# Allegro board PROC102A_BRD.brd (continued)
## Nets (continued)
DGND: C1.1 C2.2 C3.2 C4.2 C5.2 C6.2 C7.2 C8.2 C9.2 C10.2 C15.2 C16.2 C17.2 C20.2 C21.2 C22.2 C25.2 C26.2 C27.2 C30.2 C31.2 C32.2 C33.2 C34.2 C35.2 C44.2 C45.2 C46.2 C63.2 C64.2 C65.2 C66.2 C67.2 C68.2 C69.2 C70.2 C71.2 C72.2 C73.2 C74.2 C75.2 C76.2 C77.2 C78.2 C79.2 C80.2 C81.2 C82.2 C83.2 C84.2 C85.2 C86.2 C87.2 C88.2 C89.2 C90.2 C91.2 C92.2 C93.2 C94.2 C95.2 C96.2 C97.2 C98.2 C99.2 C100.2 C101.2 C102.2 C103.2 C104.2 C105.2 C106.2 C107.2 C108.2 C109.2 D13.1(K) D14.1(K) D15.2(ANODE) DN1.3 DN2.3 DN3.3 DN4.3 DN5.3 DN6.3 DN7.3 DN8.3 J1.A6 J1.A10 J1.A16 J1.A18 J1.A23 J1.A24 J1.A25 J1.B3 J1.B5 J1.B6 J1.B10 J1.B16 J1.B18 J1.B19 J1.B23 J1.B25 J1.B26 J1.B27 J1.B28 J1.B30 J1.C4 J1.C7 J1.C10 J1.C13 J1.C16 J1.C17 J1.C18 J1.C19 J1.C20 J1.C25 J1.C30 J1.D4 J1.D7 J1.D10 J1.D13 J1.D16 J1.D20 J1.D25 J1.D30 J1.E5 J1.E6 J1.E7 J1.E10 J1.E16 J1.E20 J1.E22 J1.E25 J1.E28 J1.E29 J2.2 J2.4 J2.6 J2.8 J2.10 J2.12 J2.14 J2.16 J2.18 J2.20 J3.2 J3.4 J3.6 J3.8 J3.10 J3.12 J3.14 J3.16 J3.18 J3.20 J4.2 J4.4 J4.6 J4.8 J4.10 J4.12 J4.14 J4.16 J4.18 J4.20 J5.2 J5.4 J5.6 J5.8 J5.10 J5.12 J5.14 J5.16 J5.18 J5.20 J6.2 J6.4 J6.6 J6.8 J6.10 J6.12 J6.14 J6.16 J6.18 J6.20 J7.2 J7.4 J7.6 J7.8 J7.10 J7.12 J7.14 J7.16 J7.18 J7.20 J8.2 J8.4 J8.6 J8.8 J8.10 J8.12 J8.14 J8.16 J8.18 J8.20 J9.2 J9.4 J9.6 J9.8 J9.10 J9.12 J9.14 J9.16 J9.18 J9.20 J11.3 J13.2 J13.3 J17.2 J17.4 J17.6 J18.5 J21.9 LD3.1(CATHODE) LD4.1(CATHODE) LD22.1(CATHODE) Q1.2(S) Q2.2(S) Q3.2(S) R1.1 R6.2 R7.2 R8.2 R69.2 R70.2 R73.2 R74.2 R75.2 R78.2 R79.2 R80.2 R82.2 R84.2 R85.2 R86.2 R87.2 R90.2 R91.2 R92.2 R93.2 R96.2 R97.2 R104.2 R105.2 R106.1 R107.2 R108.2 R109.1 R123.1 R124.1 R125.2 TP4.1(TP) TP5.1(TP) TP6.1(TP) TP36.1(TP) U1.4(VSS) U2.3(GND#3) U2.5(GND#5) U2.7(GND#7) U2.9(GND#9) U2.11(GND#11) U2.13(GND#13) U2.16(GND#16) U2.18(GND#18) U2.20(GND#20) U2.22(GND#22) U2.27(GND#27) U2.30(GND#30) U2.33(GND#33) U2.37(GND#37) U2.40(GND#40) U2.43(GND#43) U2.46(GND#46) U4.3(GND#3) U4.5(GND#5) U4.7(GND#7) U4.9(GND#9) U4.11(GND#11) U4.13(GND#13) U4.16(GND#16) U4.18(GND#18) U4.20(GND#20) U4.22(GND#22) U4.27(GND#27) U4.30(GND#30) U4.33(GND#33) U4.37(GND#37) U4.40(GND#40) U4.43(GND#43) U4.46(GND#46) U7.3(GND#3) U7.5(GND#5) U7.7(GND#7) U7.9(GND#9) U7.11(GND#11) U7.13(GND#13) U7.16(GND#16) U7.18(GND#18) U7.20(GND#20) U7.22(GND#22) U7.27(GND#27) U7.30(GND#30) U7.33(GND#33) U7.37(GND#37) U7.40(GND#40) U7.43(GND#43) U7.46(GND#46) U9.3(GND#3) U9.5(GND#5) U9.7(GND#7) U9.9(GND#9) U9.11(GND#11) U9.13(GND#13) U9.16(GND#16) U9.18(GND#18) U9.20(GND#20) U9.22(GND#22) U9.27(GND#27) U9.30(GND#30) U9.33(GND#33) U9.37(GND#37) U9.40(GND#40) U9.43(GND#43) U9.46(GND#46) U11.3(GND#3) U11.5(GND#5) U11.7(GND#7) U11.9(GND#9) U11.11(GND#11) U11.13(GND#13) U11.16(GND#16) U11.18(GND#18) U11.20(GND#20) U11.22(GND#22) U11.27(GND#27) U11.30(GND#30) U11.33(GND#33) U11.37(GND#37) U11.40(GND#40) U11.43(GND#43) U11.46(GND#46) U12.3(GND#3) U12.5(GND#5) U12.7(GND#7) U12.9(GND#9) U12.11(GND#11) U12.13(GND#13) U12.16(GND#16) U12.18(GND#18) U12.20(GND#20) U12.22(GND#22) U12.27(GND#27) U12.30(GND#30) U12.33(GND#33) U12.37(GND#37) U12.40(GND#40) U12.43(GND#43) U12.46(GND#46) U17.3(GND#3) U17.5(GND#5) U17.7(GND#7) U17.9(GND#9) U17.11(GND#11) U17.13(GND#13) U17.16(GND#16) U17.18(GND#18) U17.20(GND#20) U17.22(GND#22) U17.27(GND#27) U17.30(GND#30) U17.33(GND#33) U17.37(GND#37) U17.40(GND#40) U17.43(GND#43) U17.46(GND#46) U26.1(GND) U26.21(BLANK) U27.7(L-) U27.11(EP) U28.7(L-) U28.11(EP) U29.7(L-) U29.11(EP) U30.7(L-) U30.11(EP) U31.7(L-) U31.11(EP) U32.7(L-) U32.11(EP) U33.7(L-) U33.11(EP) U34.7(L-) U34.11(EP) U35.1(GND#1) U35.12(GND#12) U35.29(EP) U36.1(GND#1) U36.12(GND#12) U36.29(EP) U37.28(GND) U37.29(EP) U38.3(GND) U39.6(GND) U39.10(REF2) U39.11(REF1)
VCC1V8_HSE: C2.1 C3.1 J1.C2 J1.C3 J17.5 R71.1 TP3.1(TP)
VCC3V3_IO_HSE: C1.2 C4.1 C5.1 C8.1 C9.1 C10.1 C15.1 C16.1 C17.1 C20.1 C21.1 C22.1 C25.1 C26.1 C27.1 C30.1 C31.1 C32.1 C33.1 C34.1 C35.1 C44.1 C45.1 C46.1 C63.1 C64.1 C65.1 C72.1 C73.1 C78.1 C81.1 C82.1 C85.1 C106.1 C107.1 J1.A27 J1.A28 J1.A29 J11.1 J17.3 LD6.2(ANODE) LD7.2(ANODE) LD8.2(ANODE) LD9.2(ANODE) LD10.2(ANODE) LD11.2(ANODE) LD12.2(ANODE) LD13.2(ANODE) LD14.2(ANODE) LD15.2(ANODE) LD16.2(ANODE) LD17.2(ANODE) LD18.2(ANODE) LD19.2(ANODE) LD20.2(ANODE) LD21.2(ANODE) R2.1 R3.1 R4.1 R5.1 R64.1 R65.1 R67.1 R68.1 R76.2 R77.2 R81.2 R83.2 R88.2 R89.2 R94.2 R95.2 R98.2 R99.1 R100.2 R101.2 R102.1 R103.2 R120.1 TP2.1(TP) U1.8(VCC) U2.1(VDD#1) U2.6(VDD#6) U2.12(VDD#12) U2.19(VDD#19) U2.36(VDD#36) U4.1(VDD#1) U4.6(VDD#6) U4.12(VDD#12) U4.19(VDD#19) U4.36(VDD#36) U7.1(VDD#1) U7.6(VDD#6) U7.12(VDD#12) U7.19(VDD#19) U7.36(VDD#36) U9.1(VDD#1) U9.6(VDD#6) U9.12(VDD#12) U9.19(VDD#19) U9.36(VDD#36) U11.1(VDD#1) U11.6(VDD#6) U11.12(VDD#12) U11.19(VDD#19) U11.36(VDD#36) U12.1(VDD#1) U12.6(VDD#6) U12.12(VDD#12) U12.19(VDD#19) U12.36(VDD#36) U17.1(VDD#1) U17.6(VDD#6) U17.12(VDD#12) U17.19(VDD#19) U17.36(VDD#36) U26.24(VCC) U27.1(VCC_IN/OUT) U28.1(VCC_IN/OUT) U29.1(VCC_IN/OUT) U30.1(VCC_IN/OUT) U31.1(VCC_IN/OUT) U32.1(VCC_IN/OUT) U33.1(VCC_IN/OUT) U34.1(VCC_IN/OUT) U39.9(VS)
VCC_5V0_HSE: C6.1 C7.1 J1.A1 J1.A2 J1.A3 J17.1 R66.1 TP1.1(TP)
VCC_24V0: C66.1 C67.1 C68.1 C69.1 C70.1 C71.1 C74.1 C75.1 C76.1 C77.1 C79.1 C80.1 C83.1 C84.1 C86.1 C87.1 C88.1 C89.1 C108.1 C109.1 J21.1 R130.2 TP37.1(TP) U27.9(L+) U28.9(L+) U29.9(L+) U30.9(L+) U31.9(L+) U32.9(L+) U33.9(L+) U34.9(L+) U35.20(VS#20) U35.21(VS#21) U35.22(VS#22) U35.23(VS#23) U36.20(VS#20) U36.21(VS#21) U36.22(VS#22) U36.23(VS#23) U39.1(IS-_1) U39.2(IS-_2) U39.3(IS-_3)
AIN_0: C105.1 D10.2(A) J12.15 R128.2
AIN_2: C103.1 J12.6 R126.1
AIN_4: C104.1 D9.2(A) J12.10 R127.1
CQ_1: D1.2(A) DN1.4 U27.8(CQ)
CQ_2: D2.2(A) DN2.4 U28.8(CQ)
CQ_3: D4.2(A) DN3.4 U30.8(CQ)
CQ_4: D3.2(A) DN4.4 U29.8(CQ)
CQ_5: D6.2(A) DN5.4 U31.8(CQ)
CQ_6: D5.2(A) DN6.4 U32.8(CQ)
CQ_7: D8.2(A) DN7.4 U33.8(CQ)
CQ_8: D7.2(A) DN8.4 U34.8(CQ)
DI_1: DN1.2 J21.3 R111.1
DI_2: DN2.2 J21.2 R112.1
DI_3: DN3.2 J21.5 R113.1
DI_4: DN4.2 J21.4 R114.1
DI_5: DN5.2 J21.7 R115.1
DI_6: DN6.2 J21.6 R116.1
DI_7: DN7.2 J21.8 R117.1
DI_8: DN8.2 J21.10 R118.1
EEPROM0_A0: R2.2 R6.1 U1.1(A0)
EEPROM0_A1: R3.2 R7.1 U1.2(A1)
EEPROM0_A2: R4.2 R8.1 U1.3(A2)
EEPROM0_WP: R5.2 U1.7(WP)
EN_L+1: U7.44(1B2) U36.5(IN3)
EN_L+2: U7.39(2B2) U36.6(IN4)
EN_L+3: U7.32(4B2) U36.4(IN2)
EN_L+4: U7.31(5B2) U36.3(IN1)
EN_L+5: U7.45(0B2) U35.5(IN3)
EN_L+6: U7.26(6B2) U35.6(IN4)
EN_L+7: U7.38(3B2) U35.4(IN2)
EN_L+8: U7.25(7B2) U35.3(IN1)
EN_PHY_1: TP9.1(TP) U9.45(0B2) U27.5(EN)
EN_PHY_2: TP12.1(TP) U9.44(1B2) U28.5(EN)
EN_PHY_3: TP15.1(TP) U9.39(2B2) U30.5(EN)
EN_PHY_4: TP18.1(TP) U9.38(3B2) U29.5(EN)
EN_PHY_5: TP21.1(TP) U9.32(4B2) U31.5(EN)
EN_PHY_6: TP24.1(TP) U9.31(5B2) U32.5(EN)
EN_PHY_7: TP27.1(TP) U9.26(6B2) U33.5(EN)
EN_PHY_8: TP30.1(TP) U9.25(7B2) U34.5(EN)
FAULT_1: R76.1 U11.45(0B2) U27.2(NFAULT)
FAULT_2: R77.1 U11.44(1B2) U28.2(NFAULT)
FAULT_3: R83.1 U11.39(2B2) U30.2(NFAULT)
FAULT_4: R81.1 U11.38(3B2) U29.2(NFAULT)
FAULT_5: R89.1 U11.32(4B2) U31.2(NFAULT)
FAULT_6: R88.1 U11.31(5B2) U32.2(NFAULT)
FAULT_7: R95.1 U11.26(6B2) U33.2(NFAULT)
FAULT_8: R94.1 U11.25(7B2) U34.2(NFAULT)
GPMC0_AD0: J1.E14 U11.2(A0)
GPMC0_AD0_HDR: J6.1 U11.48(0B1)
GPMC0_AD1: J1.D14 U11.4(A1)
GPMC0_AD1_HDR: J6.3 U11.47(1B1)
GPMC0_AD2: J1.C14 U11.8(A2)
GPMC0_AD2_HDR: J6.5 U11.42(2B1)
GPMC0_AD3: J1.E15 U11.10(A3)
GPMC0_AD3_HDR: J6.7 U11.41(3B1)
GPMC0_AD4: J1.D15 U11.15(A4)
GPMC0_AD4_HDR: J6.9 U11.35(4B1)
GPMC0_AD5: J1.C15 U11.17(A5)
GPMC0_AD5_HDR: J6.11 U11.34(5B1)
GPMC0_AD6: J1.E17 U11.21(A6)
GPMC0_AD6_HDR: J6.13 U11.29(6B1)
GPMC0_AD7: J1.D17 U11.23(A7)
GPMC0_AD7_HDR: J6.15 U11.28(7B1)
GPMC0_AD8: J1.A22 J6.17
GPMC0_AD9: J1.A21 J6.19
GPMC0_AD10: J1.B21 J7.1
GPMC0_AD11: J1.E21 J7.3
GPMC0_AD12: J1.C21 J7.5
GPMC0_AD13: J1.D21 J7.7
GPMC0_AD14: J1.B20 J7.9
GPMC0_AD15: J1.A19 J7.11
GPMC0_CSN1: J1.E19 J7.17
GPMC0_CSN2: J1.D18 J7.13
GPMC0_CSN3: J1.D19 J7.15
GPMC0_DIR: J1.E18 J7.19
H_CS: R105.1 R128.1 U35.10(CS)
H_DIAG: R100.1 U35.14(DIAG_EN)
H_FAULT: R99.2 U12.26(6B2) U35.9(F\A\U\L\T\)
H_SEH: U12.32(4B2) U35.7(SEH)
H_SEL: U12.31(5B2) U35.8(SEL)
H_THERM: R98.1 R106.2 U35.13(THER)
HSE_DETECT: J1.E4 R1.2
HSE_GPIO0_31: J1.B22 U12.15(A4)
HSE_GPIO0_31_HDR: J8.1 U12.35(4B1)
HSE_GPIO0_32: J1.C22 U12.17(A5)
HSE_GPIO0_32_HDR: J8.3 U12.34(5B1)
HSE_GPIO0_33: J1.D22 U12.21(A6)
HSE_GPIO0_33_HDR: J8.5 U12.29(6B1)
HSE_GPIO0_34: J1.C23 U12.10(A3)
HSE_GPIO0_34_HDR: J8.7 U12.41(3B1)
HSE_GPIO0_35: J1.B24 U12.4(A1)
HSE_GPIO0_35_HDR: J8.9 U12.47(1B1)
HSE_GPIO0_36: J1.A20 U12.2(A0)
HSE_GPIO0_36_HDR: J8.11 U12.48(0B1)
HSE_GPIO0_37: J1.C24 U12.8(A2)
HSE_GPIO0_37_HDR: J8.13 U12.42(2B1)
HSE_GPIO0_38: J1.E26 J8.15
HSE_GPIO0_39: J1.C26 J8.17
HSE_GPIO0_41: J1.D26 J8.19
HSE_MCAN0_RX/UART4_TXD: J1.E24 J3.19
HSE_MCAN0_TX/UART4_RXD: J1.D24 J3.17
HSE_MCAN1_RX/I2C3_SDA: J1.C29 J3.15
HSE_MCAN1_TX/I2C3_SCL: J1.D29 J3.13
IN+: U39.16(IN+) U39.17(SH+)
IN-: U39.4(SH-) U39.5(IN-)
IN_CS: R126.2 U39.13(OUT)
INPUT_24V0: D15.1(CATHODE) F1.2 R131.1 U39.18(IS+_1) U39.19(IS+_2) U39.20(IS+_3)
L+_1: DN1.1 U36.17(OUT3_1) U36.18(OUT3_2)
L+_2: DN2.1 U36.15(OUT4_1) U36.16(OUT4_2)
L+_3: DN3.1 U36.25(OUT2_1) U36.26(OUT2_2)
L+_4: DN4.1 U36.27(OUT1_1) U36.28(OUT1_2)
L+_5: DN5.1 U35.17(OUT3_1) U35.18(OUT3_2)
L+_6: DN6.1 U35.15(OUT4_1) U35.16(OUT4_2)
L+_7: DN7.1 U35.25(OUT2_1) U35.26(OUT2_2)
L+_8: DN8.1 U35.27(OUT1_1) U35.28(OUT1_2)
L_CS: R108.1 R127.2 U36.10(CS)
L_DIAG: R103.1 U36.14(DIAG_EN)
L_FAULT: R102.2 U12.45(0B2) U36.9(F\A\U\L\T\)
L_SEH: U12.38(3B2) U36.7(SEH)
L_SEL: U12.44(1B2) U36.8(SEL)
L_THERM: R101.1 R109.2 U36.13(THER)
LATCH: U17.39(2B2) U26.4(LAT)
LED_G1: LD21.1(CATHODE) U26.20(OUT15)
LED_G2: LD19.1(CATHODE) U26.18(OUT13)
LED_G3: LD17.1(CATHODE) U26.16(OUT11)
LED_G4: LD15.1(CATHODE) U26.14(OUT9)
LED_G5: LD13.1(CATHODE) U26.12(OUT7)
LED_G6: LD11.1(CATHODE) U26.10(OUT5)
LED_G7: LD9.1(CATHODE) U26.8(OUT3)
LED_G8: LD7.1(CATHODE) U26.6(OUT1)
LED_R1: LD20.1(CATHODE) U26.19(OUT14)
LED_R2: LD18.1(CATHODE) U26.17(OUT12)
LED_R3: LD16.1(CATHODE) U26.15(OUT10)
LED_R4: LD14.1(CATHODE) U26.13(OUT8)
LED_R5: LD12.1(CATHODE) U26.11(OUT6)
LED_R6: LD10.1(CATHODE) U26.9(OUT4)
LED_R7: LD8.1(CATHODE) U26.7(OUT2)
LED_R8: LD6.1(CATHODE) U26.5(OUT0)
LOAD_PULSE_SE: R121.1 U12.39(2B2)
MCU_PORZ: J1.E30 J18.6 TP33.1(TP)
MCU_RESETSTATZ: J1.E3 J18.4 TP32.1(TP)
MCU_RESETZ: J1.D3 J18.2 TP31.1(TP)
MUX_CONTROL_1: R72.1 U2.24(SEL) U4.24(SEL) U7.24(SEL) U9.24(SEL) U11.24(SEL) U12.24(SEL) U17.24(SEL)
PRG0_HSE_ETH1_CLK: J1.A17 J18.3 TP35.1(TP)
PRG0_HSE_ETH2_CLK: J1.B17 J18.1 TP34.1(TP)
PRG0_MDIO0_MDC: J1.A5 J5.19
PRG0_MDIO0_MDIO: J1.A4 J5.17
PRG0_PRU0GPO0: J1.B12 Q1.1(G) R69.1 U2.2(A0)
PRG0_PRU0GPO0_HDR: J2.1 U2.48(0B1)
PRG0_PRU0GPO1: J1.E8 U2.4(A1)
PRG0_PRU0GPO1_HDR: J2.3 U2.47(1B1)
PRG0_PRU0GPO2: J1.A8 U2.8(A2)
PRG0_PRU0GPO2_HDR: J2.5 U2.42(2B1)
PRG0_PRU0GPO3: J1.A9 U2.10(A3)
PRG0_PRU0GPO3_HDR: J2.7 U2.41(3B1)
PRG0_PRU0GPO4: J1.A13 U2.15(A4)
PRG0_PRU0GPO4_HDR: J2.9 U2.35(4B1)
PRG0_PRU0GPO5: J1.C6 U2.17(A5)
PRG0_PRU0GPO5_HDR: J2.11 U2.34(5B1)
PRG0_PRU0GPO6: J1.D8 U2.21(A6)
PRG0_PRU0GPO6_HDR: J2.13 U2.29(6B1)
PRG0_PRU0GPO7: J1.B7 U2.23(A7)
PRG0_PRU0GPO7_HDR: J2.15 U2.28(7B1)
PRG0_PRU0GPO8: J1.A7 U4.2(A0)
PRG0_PRU0GPO8_HDR: J2.17 U4.48(0B1)
PRG0_PRU0GPO11: J1.B14 U4.4(A1)
PRG0_PRU0GPO11_HDR: J2.19 U4.47(1B1)
PRG0_PRU0GPO12: J1.A14 U4.8(A2)
PRG0_PRU0GPO12_HDR: J3.1 U4.42(2B1)
PRG0_PRU0GPO13: J1.C5 U4.10(A3)
PRG0_PRU0GPO13_HDR: J3.3 U4.41(3B1)
PRG0_PRU0GPO14: J1.C9 U4.15(A4)
PRG0_PRU0GPO14_HDR: J3.5 U4.35(4B1)
PRG0_PRU0GPO15: J1.D12 U4.17(A5)
PRG0_PRU0GPO15_HDR: J3.7 U4.34(5B1)
PRG0_PRU0GPO16: J1.E9 U4.21(A6)
PRG0_PRU0GPO16_HDR: J3.9 U4.29(6B1)
PRG0_PRU0GPO17: J1.B8 U4.23(A7)
PRG0_PRU0GPO17_HDR: J3.11 U4.28(7B1)
PRG0_PRU0GPO18: J1.B9 U7.4(A1)
PRG0_PRU0GPO18_HDR: J4.1 U7.47(1B1)
PRG0_PRU0GPO19: J1.B11 U7.8(A2)
PRG0_PRU0GPO19_HDR: J4.3 U7.42(2B1)
PRG0_PRU1GPO0: J1.A12 Q2.1(G) R70.1 U7.15(A4)
PRG0_PRU1GPO0_HDR: J4.5 U7.35(4B1)
PRG0_PRU1GPO1: J1.A11 U7.17(A5)
PRG0_PRU1GPO1_HDR: J4.7 U7.34(5B1)
PRG0_PRU1GPO2: J1.D9 U7.2(A0)
PRG0_PRU1GPO2_HDR: J4.9 U7.48(0B1)
PRG0_PRU1GPO3: J1.C8 U7.21(A6)
PRG0_PRU1GPO3_HDR: J4.11 U7.29(6B1)
PRG0_PRU1GPO4: J1.B13 U7.10(A3)
PRG0_PRU1GPO4_HDR: J4.13 U7.41(3B1)
PRG0_PRU1GPO5: J1.D6 U7.23(A7)
PRG0_PRU1GPO5_HDR: J4.15 U7.28(7B1)
PRG0_PRU1GPO6: J1.E11 U9.2(A0)
PRG0_PRU1GPO6_HDR: J4.17 U9.48(0B1)
PRG0_PRU1GPO8: J1.B4 U9.4(A1)
PRG0_PRU1GPO8_HDR: J4.19 U9.47(1B1)
PRG0_PRU1GPO11: J1.D11 U9.8(A2)
PRG0_PRU1GPO11_HDR: J5.1 U9.42(2B1)
PRG0_PRU1GPO12: J1.B15 U9.10(A3)
PRG0_PRU1GPO12_HDR: J5.3 U9.41(3B1)
PRG0_PRU1GPO13: J1.D5 U9.15(A4)
PRG0_PRU1GPO13_HDR: J5.5 U9.35(4B1)
PRG0_PRU1GPO14: J1.E12 U9.17(A5)
PRG0_PRU1GPO14_HDR: J5.7 U9.34(5B1)
PRG0_PRU1GPO15: J1.C11 U9.21(A6)
PRG0_PRU1GPO15_HDR: J5.9 U9.29(6B1)
PRG0_PRU1GPO16: J1.A15 U9.23(A7)
PRG0_PRU1GPO16_HDR: J5.11 U9.28(7B1)
PRG1_PRU1GPO18: J1.E13 J5.13
PRG1_PRU1GPO19: J1.C12 J5.15
RX_1: TP8.1(TP) U2.45(0B2) U27.3(RX)
RX_2: TP11.1(TP) U2.44(1B2) U28.3(RX)
RX_3: TP14.1(TP) U2.39(2B2) U30.3(RX)
RX_4: TP17.1(TP) U2.38(3B2) U29.3(RX)
RX_5: TP20.1(TP) U2.32(4B2) U31.3(RX)
RX_6: TP23.1(TP) U2.31(5B2) U32.3(RX)
RX_7: TP26.1(TP) U2.26(6B2) U33.3(RX)
RX_8: TP29.1(TP) U2.25(7B2) U34.3(RX)
SOC_I2C0_SCL: J1.E1 U1.6(SCL)
SOC_I2C0_SDA: J1.E2 U1.5(SDA)
SOC_SPI1_CLK: J1.C1 U17.15(A4)
SOC_SPI1_CLK_HDR: J9.5 U17.35(4B1)
SOC_SPI1_CLK_SE/LED: R119.2 U17.32(4B2) U26.3(SCLK)
SOC_SPI1_CS0: J1.D1 U17.10(A3)
SOC_SPI1_CS0_HDR: J9.7 U17.41(3B1)
SOC_SPI1_CS0_SE: R122.1 U17.38(3B2)
SOC_SPI1_CS1: J1.D2 U17.8(A2)
SOC_SPI1_CS1_HDR: J9.9 U17.42(2B1)
SOC_SPI1_MISO: J1.B1 U17.2(A0)
SOC_SPI1_MISO_HDR: J9.1 U17.48(0B1)
SOC_SPI1_MISO_SE: R120.2 U17.45(0B2) U38.4(Y)
SOC_SPI1_MOSI: J1.B2 U17.4(A1)
SOC_SPI1_MOSI_HDR: J9.3 U17.47(1B1)
SOC_SPI1_MOSI_LED: U17.44(1B2) U26.2(SIN)
TX_1: D16.2(A) TP7.1(TP) U4.45(0B2) U27.4(TX)
TX_2: D17.2(A) TP10.1(TP) U4.44(1B2) U28.4(TX)
TX_3: D18.2(A) TP13.1(TP) U4.39(2B2) U30.4(TX)
TX_4: D19.2(A) TP16.1(TP) U4.38(3B2) U29.4(TX)
TX_5: D20.2(A) TP19.1(TP) U4.32(4B2) U31.4(TX)
TX_6: D21.2(A) TP22.1(TP) U4.31(5B2) U32.4(TX)
TX_7: D22.2(A) TP25.1(TP) U4.26(6B2) U33.4(TX)
TX_8: D23.2(A) TP28.1(TP) U4.25(7B2) U34.4(TX)
N16728800: R104.1 U35.11(CL)
N16729761: R107.1 U36.11(CL)
N16731521: C95.1 R111.2 U37.3(IP0)
N16731525: C96.1 R112.2 U37.5(IP1)
N16731545: C97.1 R113.2 U37.7(IP2)
N16731549: C98.1 R114.2 U37.9(IP3)
N16731553: C99.1 R115.2 U37.11(IP4)
N16731557: C100.1 R116.2 U37.18(IP5)
N16731561: C101.1 R117.2 U37.20(IP6)
N16731565: C102.1 R118.2 U37.22(IP7)
N16731823: R123.2 U37.1(DB0)
N16731831: R124.2 U37.2(DB1)
N16731839: R122.2 U37.24(C\E\)
N16731843: R125.1 U37.13(RLIM)
N16732073: C90.1 C91.1 R130.1 U37.14(VCC)
N16732201: U37.23(SOP) U38.2(A)
N16798390: R121.2 U37.26(L\D\)
N16811368: F1.1 J13.1
N16812824: D10.1(K) D12.2(A)
N16812834: D12.1(K) D14.2(A)
N16813069: D9.1(K) D11.2(A)
N16813071: D11.1(K) D13.2(A)
N16970041: R82.1 U30.6(ILIM_ADJ)
N16970059: D4.1(K) Q7.3(COLLECTOR)
N17109412: R119.1 U37.25(CLK)
N17175087: R74.1 U27.6(ILIM_ADJ)
N17175103: D1.1(K) Q4.3(COLLECTOR)
N17184096: R75.1 U28.6(ILIM_ADJ)
N17184112: D2.1(K) Q5.3(COLLECTOR)
N17184793: R80.1 U29.6(ILIM_ADJ)
N17184817: D3.1(K) Q6.3(COLLECTOR)
N17188199: J11.2 R72.2
N17189922: R73.1 U26.23(IREF)
N17190440: LD1.2(ANODE) R64.2
N17190442: LD1.1(CATHODE) Q1.3(D)
N17190473: LD2.2(ANODE) R65.2
N17190482: LD2.1(CATHODE) Q2.3(D)
N17190504: LD5.1(CATHODE) Q3.3(D)
N17190506: LD5.2(ANODE) R68.2
N17190525: Q3.1(G) R71.2
N17190539: LD4.2(ANODE) R67.2
N17190541: LD3.2(ANODE) R66.2
N17194207: R87.1 U32.6(ILIM_ADJ)
N17194223: D5.1(K) Q9.3(COLLECTOR)
N17194517: R86.1 U31.6(ILIM_ADJ)
N17194572: D6.1(K) Q8.3(COLLECTOR)
N17194628: R92.1 U34.6(ILIM_ADJ)
N17194647: D7.1(K) Q10.3(COLLECTOR)
N17196536: R93.1 U33.6(ILIM_ADJ)
N17196560: D8.1(K) Q11.3(COLLECTOR)
N17284137: D16.1(K) Q4.1(BASE)
N17284170: D17.1(K) Q5.1(BASE)
N17284203: D18.1(K) Q7.1(BASE)
N17284241: D19.1(K) Q6.1(BASE)
N17284279: D20.1(K) Q8.1(BASE)
N17284317: D21.1(K) Q9.1(BASE)
N17284361: D22.1(K) Q11.1(BASE)
N17284397: D23.1(K) Q10.1(BASE)
N169701040: Q7.2(EMITTER) R85.1
N169703320: LD22.2(ANODE) R131.2
N171751400: Q4.2(EMITTER) R78.1
N171841470: Q5.2(EMITTER) R79.1
N171847351: Q6.2(EMITTER) R84.1
N171943770: Q8.2(EMITTER) R90.1
N171944000: Q9.2(EMITTER) R91.1
N171947950: Q10.2(EMITTER) R96.1
N171966200: Q11.2(EMITTER) R97.1

Pads without a net: DN1 5; DN2 5; DN3 5; DN4 5; DN5 5; DN6 5; DN7 5; DN8 5; J1 A26 A30 B29 C27 C28 D23 D27 D28 E23 E27; J9 11 13 15 17 19; J12 1 2 3 4 5 7 8 9 11 12 13 14 16 17 18 19 20; NOREF#3 1; NOREF#5 1; NOREF#6 1; NOREF#7 1; NOREF#8 1; NOREF#9 1; NOREF#10 1; NOREF#11 1; NOREF#12 1; NOREF#13 1; NOREF#14 1; NOREF#15 1; NOREF#16 1; NOREF#17 1; NOREF#18 1; NOREF#19 1; NOREF#20 1; NOREF#21 1; NOREF#22 1; NOREF#23 1; NOREF#24 1; NOREF#25 1; NOREF#26 1; NOREF#27 1; NOREF#29 1; NOREF#30 1; NOREF#31 1; NOREF#32 1; NOREF#33 1; NOREF#34 1; NOREF#35 1; NOREF#36 1; NOREF#37 1; NOREF#38 1; NOREF#39 1; NOREF#40 1; NOREF#41 1; NOREF#42 1; NOREF#43 1; NOREF#44 1; NOREF#45 1; NOREF#46 1; NOREF#47 1; NOREF#48 1; NOREF#49 1; NOREF#50 1; NOREF#51 1; NOREF#52 1; NOREF#53 1; NOREF#54 1; NOREF#55 1; NOREF#56 1; NOREF#57 1; NOREF#60 1; NOREF#61 1; NOREF#62 1; NOREF#63 1; NOREF#64 1; NOREF#65 1; NOREF#66 1; NOREF#67 1; NOREF#68 1; NOREF#69 1; NOREF#71 1; NOREF#72 1; NOREF#73 1; NOREF#74 1; NOREF#75 1; NOREF#76 1; NOREF#77 1; NOREF#78 1; NOREF#79 1; NOREF#80 1; NOREF#82 1; NOREF#83 1; NOREF#84 1; NOREF#85 1; NOREF#86 1; NOREF#87 1; NOREF#88 1; NOREF#89 1; NOREF#90 1; NOREF#91 1; NOREF#92 1; NOREF#94 1; NOREF#95 1; NOREF#96 1; NOREF#97 1; NOREF#100 1; NOREF#101 1; NOREF#104 1; NOREF#105 1; NOREF#106 1; NOREF#107 1; NOREF#108 1; NOREF#109 1; NOREF#110 1; NOREF#111 1; NOREF#112 1; NOREF#113 1; NOREF#114 1; NOREF#115 1; NOREF#116 1; NOREF#117 1; NOREF#118 1; NOREF#119 1; NOREF#120 1; NOREF#121 1; NOREF#122 1; NOREF#123 1; NOREF#124 1; NOREF#125 1; NOREF#126 1; NOREF#127 1; NOREF#128 1; NOREF#129 1; NOREF#130 1; NOREF#131 1; NOREF#132 1; NOREF#133 1; NOREF#134 1; NOREF#135 1; NOREF#136 1; NOREF#137 1; NOREF#138 1; NOREF#139 1; NOREF#140 1; NOREF#141 1; NOREF#142 1; NOREF#143 1; NOREF#144 1; NOREF#146 1; NOREF#147 1; NOREF#148 1; NOREF#149 1; NOREF#150 1; NOREF#152 1; NOREF#153 1; NOREF#154 1; NOREF#155 1; NOREF#156 1; NOREF#157 1; NOREF#158 1; NOREF#159 1; NOREF#160 1; NOREF#161 1; NOREF#162 1; NOREF#163 1; NOREF#164 1; NOREF#165 1; NOREF#166 1; NOREF#167 1; NOREF#168 1; NOREF#169 1; NOREF#170 1; NOREF#171 1; NOREF#172 1; NOREF#173 1; NOREF#174 1; NOREF#175 1; NOREF#176 1; NOREF#177 1; NOREF#178 1; NOREF#179 1; NOREF#180 1; NOREF#181 1; NOREF#182 1; NOREF#183 1; NOREF#184 1; NOREF#185 1; NOREF#186 1; NOREF#187 1; NOREF#188 1; NOREF#189 1; NOREF#191 1; NOREF#192 1; NOREF#193 1; NOREF#194 1; NOREF#195 1; NOREF#196 1; NOREF#197 1; NOREF#198 1; NOREF#199 1; NOREF#200 1; NOREF#201 1; NOREF#202 1; NOREF#203 1; NOREF#205 1; NOREF#206 1; NOREF#207 1; NOREF#209 1; NOREF#211 1; NOREF#212 1; NOREF#213 1; NOREF#214 1; NOREF#216 1; NOREF#217 1; NOREF#218 1; NOREF#219 1; NOREF#220 1; NOREF#221 1; NOREF#222 1; NOREF#223 1; NOREF#224 1; NOREF#225 1; NOREF#226 1; NOREF#227 1; NOREF#228 1; NOREF#229 1; NOREF#230 1; NOREF#231 1; NOREF#233 1; NOREF#234 1; NOREF#235 1; NOREF#236 1; NOREF#237 1; NOREF#238 1; NOREF#239 1; NOREF#240 1; NOREF#241 1; NOREF#242 1; NOREF#243 1; NOREF#244 1; NOREF#245 1; NOREF#246 1; NOREF#247 1; NOREF#248 1; NOREF#249 1; NOREF#250 1; NOREF#251 1; NOREF#252 1; NOREF#254 1; NOREF#255 1; NOREF#256 1; NOREF#257 1; NOREF#258 1; NOREF#259 1; NOREF#260 1; NOREF#261 1; NOREF#262 1; NOREF#263 1; NOREF#264 1; NOREF#265 1; NOREF#266 1; NOREF#267 1; NOREF#268 1; NOREF#269 1; NOREF#270 1; NOREF#271 1; NOREF#272 1; NOREF#273 1; NOREF#274 1; NOREF#275 1; NOREF#276 1; NOREF#277 1; NOREF#278 1; NOREF#280 1; NOREF#281 1; NOREF#283 1; NOREF#284 1; NOREF#285 1; NOREF#286 1; NOREF#287 1; NOREF#288 1; NOREF#289 1; NOREF#291 1; NOREF#292 1; NOREF#294 1; NOREF#295 1; NOREF#296 1; NOREF#297 1; NOREF#298 1; NOREF#299 1; NOREF#300 1; NOREF#301 1; NOREF#302 1; NOREF#303 1; NOREF#304 1; NOREF#305 1; NOREF#306 1; NOREF#307 1; NOREF#308 1; NOREF#309 1; NOREF#310 1; NOREF#311 1; NOREF#313 1; NOREF#315 1; NOREF#316 1; NOREF#317 1; NOREF#318 1; NOREF#319 1; NOREF#320 1; NOREF#321 1; NOREF#322 1; NOREF#323 1; NOREF#324 1; NOREF#325 1; NOREF#326 1; NOREF#327 1; NOREF#329 1; NOREF#331 1; NOREF#332 1; NOREF#333 1; NOREF#334 1; NOREF#335 1; NOREF#336 1; NOREF#337 1; NOREF#338 1; NOREF#339 1; NOREF#340 1; NOREF#341 1; NOREF#342 1; NOREF#345 1; NOREF#346 1; NOREF#348 1; NOREF#349 1; NOREF#350 1; NOREF#351 1; NOREF#352 1; NOREF#353 1; NOREF#354 1; NOREF#355 1; NOREF#356 1; NOREF#357 1; NOREF#358 1; NOREF#359 1; NOREF#360 1; NOREF#361 1; NOREF#362 1; NOREF#363 1; NOREF#364 1; NOREF#365 1; NOREF#366 1; NOREF#367 1; NOREF#368 1; NOREF#369 1; NOREF#371 1; NOREF#372 1; NOREF#374 1; NOREF#375 1; NOREF#376 1; NOREF#377 1; NOREF#378 1; NOREF#379 1; NOREF#380 1; NOREF#381 1; NOREF#382 1; NOREF#383 1; NOREF#384 1; NOREF#385 1; NOREF#386 1; NOREF#387 1; NOREF#388 1; NOREF#389 1; NOREF#390 1; NOREF#392 1; NOREF#393 1; NOREF#394 1; NOREF#395 1; NOREF#396 1; NOREF#397 1; NOREF#398 1; NOREF#399 1; NOREF#400 1; NOREF#401 1; NOREF#402 1; NOREF#403 1; NOREF#404 1; NOREF#405 1; NOREF#406 1; NOREF#407 1; NOREF#408 1; NOREF#410 1; NOREF#411 1; NOREF#412 1; NOREF#413 1; NOREF#414 1; NOREF#415 1; NOREF#416 1; NOREF#417 1; NOREF#418 1; NOREF#419 1; NOREF#420 1; NOREF#421 1; NOREF#422 1; NOREF#423 1; NOREF#424 1; NOREF#425 1; NOREF#426 1; NOREF#427 1; NOREF#428 1; NOREF#429 1; NOREF#430 1; NOREF#431 1; NOREF#432 1; NOREF#433 1; NOREF#434 1; NOREF#435 1; NOREF#436 1; NOREF#437 1; NOREF#438 1; NOREF#439 1; NOREF#440 1; NOREF#441 1; NOREF#442 1; NOREF#443 1; NOREF#444 1; NOREF#445 1; NOREF#446 1; NOREF#447 1; NOREF#448 1; NOREF#449 1; NOREF#451 1; NOREF#452 1; NOREF#453 1; NOREF#454 1; NOREF#455 1; NOREF#456 1; NOREF#457 1; NOREF#458 1; NOREF#459 1; NOREF#461 1; NOREF#462 1; NOREF#463 1; NOREF#464 1; NOREF#466 1; NOREF#467 1; NOREF#470 1; NOREF#471 1; U2 14; U4 14; U7 14; U9 14; U11 14; U12 14 23 25 28; U17 14 17 21 23 25 26 28 29 31 34; U26 22; U27 10; U28 10; U29 10; U30 10; U31 10; U32 10; U33 10; U34 10; U35 2 19 24; U36 2 19 24; U37 4 6 8 10 12 16 17 19 21 27; U38 1; U39 7 8 12 14 15

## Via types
v1: diameter 0.457, hole 0.203, TOP to BOTTOM, 834 vias

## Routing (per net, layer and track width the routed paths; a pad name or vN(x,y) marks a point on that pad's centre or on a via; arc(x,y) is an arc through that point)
5VOP: length 2.3
  TOP w0.508: U38.5 101.71,20.63 C94.1 v1(102.57,20.64)
  vias: v1(108.61,27.98) v1(109.67,27.98) v1(110.73,27.98)
DGND: length 351.1
  TOP w0.305: U12.27 v1(36.93,27) ; U7.27 v1(66.24,27.11) ; R108.2 v1(71.93,92.8) ; U7.30 v1(64.74,27.11) ; U12.33 v1(33.93,27) ; U12.20 v1(35.93,21.94) ; U7.13 61.74,21.74 62.05,22.05 v1(62.24,22.05) ; R105.2 v1(86.5,92.8) ; U7.33 v1(63.24,27.11) ; U17.43 72.89,29.43 72.86,29.45 v1(72.86,29.84) ; U17.46 71.39,29.71 71.38,29.72 v1(71.38,29.76) ; U12.11 31.43,21.62 31.12,21.93 v1(31.12,21.97) ; U17.40 74.39,29.68 74.42,29.72 v1(74.42,29.97) ; v1(76.89,22.3) 76.69,22.3 76.39,21.99 U17.13 ; R104.2 v1(87.78,92.83) ; v1(57.48,22.13) 57.74,21.86 U7.5 ; U12.7 29.43,21.72 29.44,21.73 29.44,22.3 29.75,22.61 v1(29.97,22.61) 30.43,22.15 U12.9 ; U7.16 v1(63.24,22.05) ; v1(79.35,29.84) 79.39,29.8 U17.30 ; U17.3 71.39,19.32 C44.2 71.36,19.3 ; U7.3 C21.2 56.72,19.05 ; C45.2 78.59,19.58 78.89,19.88 U17.18 ; U7.40 59.74,27.13 v1(59.95,26.92) ; U12.46 v1(27.43,27) ; U7.9 59.74,21.73 59.43,22.05 v1(59.27,22.05) 59.09,22.05 58.74,21.7 U7.7 ; v1(128.65,35.56) 128.77,35.56 128.78,35.55 U26.1 ; U7.46 v1(56.74,27.11) ; U17.5 72.39,21.94 72.03,22.3 v1(71.89,22.3) ; U12.13 32.43,21.82 v1(32.84,22.22) ; U7.43 v1(58.24,27.11) ; C22.2 63.94,19.33 64.24,19.63 U7.18 ; v1(28.95,26.99) 28.93,27 U12.43 ; R107.2 v1(73.21,92.82) ; U7.22 v1(66.24,22.05) ; C46.2 76.11,30.34 75.89,30.11 U17.37 ; v1(85.22,124.21) 84.95,124.47 U39.10 ; v1(108.72,15.99) 109.15,16.42 U37.28 ; 28.45,20.7 U12.5 ; U12.40 30.43,27.27 30.19,27.03 v1(30.19,27.02) ; v1(27.5,18.01) 27.03,18.48 C33.2 27.03,19.29 27.43,19.69 U12.3 ; U17.11 75.39,21.98 75.07,22.3 v1(74.89,22.3) ; U17.33 v1(77.89,27.36) ; U12.18 34.93,19.52 34.64,19.22 C34.2 ; U17.20 v1(79.89,22.3) 79.89,22.29 80.61,22.29 80.89,22.02 U17.22 ; U12.30 v1(35.43,27) ; U7.37 61.24,30.3 C20.2 ; C35.2 31.93,30 U12.37 ; U7.20 v1(65.24,22.05) ; U17.27 80.89,29.85 v1(80.85,29.88) ; U7.11 60.74,21.73 60.42,22.05 v1(60.24,22.05) ; U12.22 v1(36.93,21.94) ; U17.16 v1(77.89,22.3) ; U12.16 v1(33.93,21.94)
  TOP w0.381: U35.1 v1(80.55,98.07) ; U39.6 v1(82.35,124.12) ; v1(138.18,36.48) 138.17,36.47 C63.2 ; U35.12 v1(87.7,97.93) ; C35.2 v1(32.16,31.08) ; v1(132.34,38.61) 132.15,38.61 132.1,38.56 R73.2 ; v1(71.36,18.44) 71.36,19.3 ; U36.12 v1(73.13,97.98) ; v1(56.72,18.19) 56.72,19.05 ; v1(63.94,18.21) C22.2 ; U36.1 v1(65.98,98.07) ; C46.2 76.11,31.54 v1(76.2,31.62) ; v1(61.3,31.21) C20.2 ; C4.2 v1(27.87,1.42) ; C34.2 v1(34.64,18.1) ; U26.21 v1(137.23,33.64) ; v1(78.59,18.46) C45.2 ; C5.2 v1(27.85,2.73)
  TOP w0.457: U39.11 v1(84.95,132.73)
  TOP w0.508: TP6.1 98.87,34.25 C1.1 v1(97.67,35.29) ; v1(114.98,31.84) 114.98,31.84 Q1.2 ; v1(116.58,30.42) C90.2 v1(115,29.17) ; v1(103.72,31.98) 103.72,31.98 Q3.2 ; v1(119.44,30.73) 119.44,30.26 C91.2 118.71,29.7 118,30.41 v1(118,30.73) ; R70.2 v1(109.28,35.76) ; C105.2 120.85,9.32 v1(121.2,9.67) ; v1(72.01,2.45) 71.97,2.41 C7.2 ; R69.2 v1(114.96,35.69) ; D13.1 v1(117.06,9.47) ; R7.2 v1(84.17,32.16) ; v1(123.29,11.44) R123.1 R124.1 ; C106.2 v1(87.93,127.97) ; C103.2 v1(103.21,8.36) ; Q2.2 109.3,31.91 v1(109.3,31.91) ; v1(73.8,2.42) C6.2 72.97,3.38 TP4.1 ; U1.4 87.99,30.4 v1(87.98,30.4) ; C93.2 v1(106.78,25.23) ; C104.2 108.93,10.89 v1(108.94,10.9) ; C107.2 v1(87.98,126.46) ; R8.2 v1(84.17,29.29) ; v1(106.45,26.84) C92.2 107.39,26.84 v1(107.39,28.05) ; U38.3 97.83,17.28 v1(97.64,17.47) ; R6.2 v1(84.19,36.06) ; C94.2 v1(102.57,21.62)
  TOP w0.635: R125.2 v1(123.99,23.98)
  TOP w0.762: v1(89.63,111.8) 89.62,111.79 C88.2 88.22,113.21 v1(88.21,113.22) ; v1(64.76,109.59) C89.2 v1(66.62,111.56)
  BOTTOM w0.305: U12.3 27.43,21.59 v1(27.81,21.97) ; U17.18 v1(78.89,22.3) ; U12.5 28.43,19.82 28.2,19.58 ; U12.9 30.46,20.74 30.46,22.33 30.18,22.61 v1(29.97,22.61) ; v1(76.71,27.3) 76.39,27.63 U2.37 ; U7.20 v1(65.24,22.05) ; U9.46 51.65,26.69 v1(51.81,26.52) ; U7.33 v1(63.24,27.11) ; U17.27 80.89,29.85 v1(80.85,29.88) ; U12.46 v1(27.43,27) ; v1(110.21,91.17) 110.45,90.93 U32.7 ; U17.20 v1(79.89,22.3) ; U17.7 73.39,20.03 73.71,19.71 C10.2 ; v1(79.35,29.84) 79.39,29.8 U17.30 ; U17.43 72.89,29.43 72.86,29.45 v1(72.86,29.84) ; U12.18 v1(34.93,21.94) ; U2.13 75.89,20.13 75.67,19.91 75.67,19.34 C9.2 ; v1(30.19,27.02) 30.19,27.03 30.43,27.27 U12.40 ; U11.13 31.93,19.77 31.72,19.55 31.72,18.98 C30.2 ; U4.11 v1(62.24,22.05) ; U9.33 45.15,26.73 v1(45.09,26.67) ; C31.2 29.76,19.35 29.43,19.67 U12.7 ; U17.40 74.39,29.68 74.42,29.72 v1(74.42,29.97) ; C16.2 66.24,19.15 U7.22 ; U12.33 v1(33.93,27) ; U9.40 v1(48.65,26.67) ; R106.1 89.48,93.86 89.91,93.43 v1(89.91,92.85) ; U2.11 v1(76.89,22.3) ; v1(59.27,22.05) 59.41,22.05 59.74,21.72 U7.9 ; U17.9 74.39,22.01 74.1,22.3 v1(73.91,22.3) ; v1(59.95,26.92) 59.74,27.13 U7.40 ; U11.11 32.93,22.13 v1(32.84,22.22) ; U17.46 71.39,29.71 71.38,29.72 v1(71.38,29.76) ; C32.2 36.93,19.04 U12.22 ; v1(75.34,92.85) 75.34,93.55 75.03,93.86 R109.1 ; U7.3 56.74,21.67 57.12,22.05 57.4,22.05 v1(57.48,22.13) 57.74,21.86 U7.5 ; U7.27 v1(66.24,27.11) ; v1(110.21,141.59) 110.45,141.35 U34.7 ; C8.2 80.89,19.4 U17.22 ; U7.46 v1(56.74,27.11) ; U17.5 72.39,21.92 72.01,22.3 v1(71.89,22.3) 71.75,22.3 71.39,21.93 U17.3 ; v1(50.07,26.67) 50.15,26.75 U9.43 ; U9.5 50.65,21.61 v1(50.66,21.62) ; U7.30 v1(64.74,27.11) ; U9.27 v1(42.15,26.67) ; U12.20 v1(35.93,21.94) ; U9.13 46.65,19.44 46.43,19.23 46.43,18.66 C27.2 ; U4.37 v1(61.74,27.11) ; U9.30 v1(43.65,26.67) ; U12.16 v1(33.93,21.94) ; v1(28.95,26.99) 28.93,27 U12.43 ; U12.27 v1(36.93,27) ; U12.30 v1(35.43,27) ; U9.16 45.15,21.22 45.07,21.29 v1(45.07,21.61) ; U9.18 44.15,19.35 44.47,19.03 C26.2 ; U9.37 47.15,26.48 v1(46.95,26.29) ; C17.2 61.03,19.09 61.03,19.66 61.24,19.88 U4.13 ; C15.2 59.06,19.47 58.74,19.79 U7.7 ; R1.1 v1(68.75,11.42) ; U7.16 v1(63.24,22.05) ; U7.43 v1(58.24,27.11) ; C25.2 51.65,18.72 U9.3 ; U17.33 v1(77.89,27.36) ; U7.18 v1(64.24,22.05) ; U9.9 v1(48.65,21.61) ; U9.7 v1(49.65,21.61) ; U9.11 v1(47.65,21.61) ; U17.16 v1(77.89,22.3) ; U11.37 v1(32.43,27)
  BOTTOM w0.381: v1(110.21,116.07) 110.22,116.07 110.47,115.82 U33.7 ; C16.2 v1(66.27,18.21) ; v1(135.48,116.45) 135.5,116.45 135.74,116.2 U28.7 ; v1(44.21,17.77) 44.22,17.79 44.22,17.8 44.47,18.04 C26.2 ; U31.7 110.47,65.02 110.22,65.27 v1(110.21,65.27) ; v1(135.6,141.9) 135.61,141.9 135.85,141.66 U27.7 ; C9.2 75.69,18.47 v1(75.66,18.43) ; v1(46.43,17.77) 46.45,17.8 C27.2 ; C8.2 v1(80.92,18.46) ; C10.2 v1(73.71,18.46) ; C15.2 v1(59.06,18.21) ; C32.2 v1(36.97,18.1) ; C31.2 29.76,18.28 v1(29.93,18.11) ; v1(135.48,91.05) 135.5,91.05 135.74,90.8 U30.7 ; C17.2 v1(61.05,18.21) ; C30.2 31.74,18.27 v1(31.47,18) ; C25.2 51.68,17.86 v1(51.64,17.82) ; U29.7 135.87,65.02 135.62,65.27 v1(135.61,65.27)
  BOTTOM w0.508: v1(105.72,112.44) 105.76,112.47 C85.2 ; J1.B27 v1(35.96,2.58) ; J1.D4 v1(66.44,6.39) ; J1.D10 v1(58.82,6.39) ; J1.B10 v1(58.82,2.58) ; J1.E5 v1(65.17,7.66) ; J1.C17 v1(48.66,3.85) ; J1.A16 v1(49.93,1.31) ; R82.2 138.67,92.12 137.83,92.96 v1(137.42,92.96) ; v1(131.08,61.64) 131.16,61.71 C72.2 ; J1.C25 v1(38.5,3.85) ; C3.2 v1(79.77,4.77) ; v1(105.72,137.97) 105.76,138 C82.2 ; R87.2 v1(114.53,91.41) ; v1(53.85,3.94) 53.85,3.97 J1.C13 ; J1.A25 v1(38.5,1.31) ; v1(139.92,141.9) 139.92,141.99 139.76,142.14 R74.2 ; J1.E22 v1(42.31,7.66) ; J1.A6 v1(63.9,2.58) J1.B6 ; J1.B30 v1(32.15,2.58) ; J1.C19 v1(46.12,3.85) ; J1.D30 v1(32.15,6.39) ; J1.C7 v1(62.63,3.85) ; J1.E16 v1(49.93,7.66) ; R93.2 v1(114.53,116.31) ; J1.E25 v1(38.5,7.66) ; J1.B16 v1(49.93,2.58) ; C64.2 131.03,112.85 v1(131,112.82) ; J1.A24 v1(39.77,1.31) ; R92.2 v1(114.53,141.83) ; C73.2 131.03,87.45 v1(131,87.42) ; v1(105.72,61.64) 105.76,61.67 C81.2 ; J1.E29 v1(33.42,7.66) ; J1.B23 v1(41.04,2.58) ; v1(105.72,87.55) 105.76,87.58 C78.2 ; J1.A10 v1(58.82,1.31) ; J1.D25 v1(38.5,6.39) ; J1.C10 v1(58.82,3.85) ; R80.2 v1(139.7,65.51) ; J1.C18 v1(47.39,3.85) ; J1.B26 v1(37.23,2.58) ; R86.2 v1(114.53,65.51) ; J1.E10 v1(58.82,7.66) ; J1.D20 45.48,5.83 v1(44.99,6.32) ; R91.2 v1(102.23,90.57) ; J1.E20 44.99,7.52 v1(44.99,7.59) ; J1.B25 v1(38.5,2.58) ; J1.B18 v1(47.39,2.58) ; J1.D7 J1.E7 v1(62.63,7.66) J1.E6 ; J1.C4 v1(66.44,3.85) ; J1.B3 v1(67.71,2.58) ; J1.E28 v1(34.69,7.66) ; J1.B19 v1(46.12,2.58) ; J1.B28 v1(34.69,2.58) ; C2.2 v1(81.22,4.78) ; J1.D16 v1(49.93,6.39) ; J1.D13 v1(55.01,6.39) ; J1.C20 v1(44.85,3.85) ; J1.C30 v1(32.15,3.85) ; J1.A23 v1(41.04,1.31) ; J1.B5 v1(65.17,2.58) ; R75.2 v1(140.28,116.69) ; J1.A18 v1(47.39,1.31) ; J1.C16 v1(49.93,3.85) ; C65.2 v1(131.14,138.31)
  BOTTOM w0.635: R79.2 v1(127.5,115.84) ; v1(105.11,25.4) C100.2 105.11,21.59 C101.2 105.06,19.59 C102.2 ; R97.2 v1(102.23,115.46) ; R85.2 v1(127.5,90.44) ; v1(127.85,64.43) 128.08,64.66 R84.2 ; C99.2 C98.2 122.54,18.47 C97.2 122.51,16.41 C96.2 122.54,14.51 C95.2 122.55,14.2 v1(123.51,13.24) ; R96.2 v1(102.23,140.99) ; R78.2 v1(127.62,141.3) ; R90.2 v1(102.23,64.66)
  vias: v1(20.83,36.2) v1(21.97,35.81) v1(22.61,52.96) v1(23.75,51.56) v1(24.13,35.81) v1(24.77,54.31) v1(25.15,32.51) v1(25.91,52.32) v1(26.93,31.75) v1(27.43,29.46) v1(27.94,16.38) v1(28.09,18.8) v1(38.23,25.4) v1(41.28,15.62) v1(42.65,21.61) v1(42.93,67.44) v1(43.69,69.98) v1(43.94,66.17) v1(44.96,16.26) v1(45.85,39.24) v1(45.85,15.88) v1(48.64,15.24) v1(49.28,17.4) v1(51.82,9.91) v1(53.34,33.02) v1(53.72,23.11) v1(54.99,31.62) v1(54.99,30.23) v1(54.99,14.6) v1(56.52,33.4) v1(56.64,36.96) v1(56.74,31.24) v1(56.77,29.84) v1(57.53,14.86) v1(58.8,31.11) v1(58.8,29.72) v1(59.06,14.99) v1(60.58,14.22) v1(62.84,24.82) v1(63.5,25.78) v1(63.5,13.97) v1(64.77,25.78) v1(66.1,103.38) v1(66.1,102.37) v1(66.1,101.35) v1(67.11,103.38) v1(67.11,102.37) v1(67.11,101.35) v1(67.15,116.65) v1(67.15,115.08) v1(67.18,113.54) v1(67.34,131.36) v1(67.34,129.76) v1(67.34,128.19) v1(67.25,124) v1(67.25,122.4) v1(67.25,120.82) v1(67.49,133.13) v1(68.13,103.38) v1(68.13,102.37) v1(68.13,101.35) v1(68.3,111.57) v1(68.33,24.33) v1(68.33,23.04) v1(68.36,131.96) v1(68.68,116.65) v1(68.78,124) v1(68.78,120.82) v1(69.15,103.38) v1(69.15,102.37) v1(69.15,101.35) v1(69.82,111.57) v1(69.92,118.92) v1(69.85,24.26) v1(69.85,23.01) v1(69.96,131.95) v1(70.16,103.38) v1(70.16,102.37) v1(70.16,101.35) v1(70.23,35.69) v1(70.23,34.42) v1(71.12,30.73) v1(71.18,103.38) v1(71.18,102.37) v1(71.18,101.35) v1(72.19,103.38) v1(72.19,102.37) v1(72.19,101.35) v1(72.9,31.37) v1(73.21,103.38) v1(73.21,102.37) v1(73.21,101.35) v1(73.41,38.48) v1(73.41,37.08) v1(74.23,103.38) v1(74.23,102.37) v1(74.23,101.35) v1(76.58,35.94) v1(76.58,34.67) v1(77.98,26.04) v1(77.98,15.88) v1(78.11,30.61) v1(80.14,25.53) v1(80.67,103.39) v1(80.67,102.37) v1(80.67,101.35) v1(80.9,26.29) v1(81.68,103.39) v1(81.68,102.37) v1(81.68,101.35) v1(82.7,103.39) v1(82.7,102.37) v1(82.7,101.35) v1(83.72,103.39) v1(83.72,102.37) v1(83.72,101.35) v1(84.73,103.39) v1(84.73,102.37) v1(84.73,101.35) v1(85.35,21.59) v1(85.75,103.39) v1(85.75,102.37) v1(85.75,101.35) v1(85.98,22.61) v1(86.71,22.06) v1(86.76,103.39) v1(86.76,102.37) v1(86.76,101.35) v1(87.78,103.39) v1(87.78,102.37) v1(87.78,101.35) v1(88.8,103.39) v1(88.8,102.37) v1(88.8,101.35) v1(94.62,25.53) v1(96.03,90.35) v1(96.78,27.43) v1(109.01,141.59) v1(109.02,140.13) v1(109.01,116.07) v1(109.02,114.61) v1(109.01,91.17) v1(109.02,89.72) v1(109.01,65.27) v1(109.02,63.81) v1(109.62,140.85) v1(109.62,115.32) v1(109.62,90.43) v1(109.62,64.52) v1(110.22,140.12) v1(110.22,114.59) v1(110.22,89.7) v1(110.22,63.79) v1(112.31,24.67) v1(112.31,23.65) v1(112.31,22.63) v1(112.31,21.62) v1(112.31,20.6) v1(112.31,19.59) v1(112.31,18.57) v1(112.31,17.55) v1(112.31,16.54) v1(113.32,24.67) v1(113.32,23.65) v1(113.32,22.63) v1(113.32,21.62) v1(113.32,20.6) v1(113.32,19.59) v1(113.32,18.57) v1(113.32,17.55) v1(113.32,16.54) v1(114.34,24.67) v1(114.34,23.65) v1(114.34,22.63) v1(114.34,21.62) v1(114.34,20.6) v1(114.34,19.59) v1(114.34,18.57) v1(114.34,17.55) v1(114.34,16.54) v1(126.42,9.91) v1(134.28,116.45) v1(134.29,114.99) v1(134.28,91.05) v1(134.29,89.59) v1(134.39,141.9) v1(134.4,140.45) v1(134.41,65.27) v1(134.42,63.81) v1(134.89,115.7) v1(134.89,90.3) v1(135.01,141.16) v1(135.02,64.52) v1(135.49,114.97) v1(135.49,89.57) v1(135.6,140.43) v1(135.62,63.79)
VCC1V8_HSE: length 14.5
  TOP w0.508: R71.1 103.71,36.25 TP3.1 99.54,40.45 v1(94.22,40.45)
  BOTTOM w0.508: J1.C3 67.71,3.85 ; J1.C2 68.98,3.85
  vias: v1(81.93,3.03) v1(82.89,3.03)
VCC3V3_IO_HSE: length 180.6
  TOP w0.305: C20.1 62.28,30.15 61.74,29.61 U7.36 ; C22.1 64.92,19.63 64.74,19.81 U7.19 ; 70.38,19.3 C44.1 U17.1 ; C35.1 33.14,30.04 32.43,29.33 U12.36 ; R101.2 74.47,92.51 v1(74.54,92.45) ; R103.2 75.73,93.18 76.05,92.86 v1(76.05,92.36) ; v1(90.86,92.4) 90.86,93.33 R100.2 ; C21.1 55.74,19.09 U7.1 ; U12.19 35.43,19.8 35.62,19.61 C34.1 ; U7.12 v1(61.24,22.05) ; v1(31.66,22.32) 31.93,22.04 U12.12 ; v1(70.15,92.36) 70.15,92.37 R102.1 ; v1(84.73,92.42) 84.72,92.43 R99.1 ; C45.1 79.57,19.86 79.39,20.05 U17.19 ; U17.36 76.39,29.57 77.09,30.27 C46.1 ; v1(89.1,92.38) 89.04,92.43 R98.2 ; U17.12 v1(75.89,22.3) ; v1(26.3,18.06) 26.05,18.31 C33.1 26.04,18.94 26.04,20.32 U12.1 ; U17.6 v1(72.89,22.3) ; U7.6 v1(58.24,22.05) ; U12.6 v1(28.93,21.94)
  TOP w0.381: U26.24 137.14,35.55 C63.1 v1(137.19,36.48) ; C46.1 77.09,31.46 v1(77.2,31.56) ; v1(55.74,18.19) 55.76,18.22 C21.1 ; C35.1 v1(33.14,31.08) ; C34.1 v1(35.62,18.1) ; v1(79.57,18.46) C45.1 ; v1(70.38,18.44) 70.38,19.3 ; v1(64.92,18.21) C22.1 ; v1(62.28,31.21) C20.1
  TOP w0.508: LD19.2 v1(149.04,110.71) ; R4.1 v1(84.17,30.68) ; LD9.2 94.68,106.55 v1(94.47,106.76) ; R2.1 v1(84.19,34.8) ; LD17.2 v1(149.04,84.66) ; R68.1 v1(107.38,37.12) ; R120.1 102.72,14.64 v1(102.73,14.62) ; R67.1 101.73,34.17 101.22,34.68 v1(101.2,34.68) 101.03,34.68 99.23,32.89 TP2.1 98.96,32.94 R5.1 v1(97.55,32.03) ; LD15.2 v1(149.04,59.6) ; LD20.2 v1(149.04,132.11) ; LD18.2 v1(149.04,106.98) ; v1(96.69,35.29) C1.2 96.65,34.21 U1.8 ; R3.1 v1(84.17,33.54) ; LD16.2 v1(149.04,81.51) ; LD11.2 v1(94.34,81.15) ; LD7.2 96.06,129.24 v1(96.52,128.78) ; LD8.2 94.8,109.95 94.22,110.52 94.22,111.24 v1(94.24,111.25) ; LD12.2 v1(94.34,59.15) ; LD6.2 96.06,135.84 v1(96.01,135.89) ; LD13.2 v1(94.34,55.75) ; LD21.2 v1(149.04,135.59) ; LD10.2 v1(94.34,84.55) ; LD14.2 v1(149.04,56.05) ; R65.1 v1(112.96,37.05) ; R64.1 v1(118.64,36.98)
  BOTTOM w0.305: U2.12 76.39,20.14 76.67,19.85 C9.1 ; v1(50.3,18.74) 50.15,18.89 U9.6 ; v1(76.63,26.49) 76.54,26.49 75.88,27.14 75.88,27.79 75.89,27.8 U2.36 ; U12.19 35.43,18.28 v1(35.62,18.1) ; U27.1 132.84,140.16 132.12,139.45 C65.1 ; C32.1 37.93,19.02 U11.1 ; C85.1 106.74,113.61 107.45,114.32 U33.1 ; v1(32.42,25.92) 31.93,26.42 31.93,27.43 31.93,27.44 U11.36 ; C30.1 32.72,19.49 32.43,19.78 U11.12 ; v1(79.57,18.46) 79.39,18.64 U17.19 ; U4.12 61.74,19.89 62.03,19.61 C17.1 ; v1(64.92,18.21) 64.74,18.39 U7.19 ; C10.1 72.73,19.87 72.89,20.03 U17.6 ; C27.1 47.43,19.17 47.15,19.46 U9.12 ; C64.1 132.01,113.99 132.72,114.7 U28.1 ; C26.1 43.49,19.19 43.65,19.35 U9.19 ; U34.1 107.45,139.85 106.74,139.14 C82.1 ; U7.6 58.24,19.78 58.08,19.62 C15.1 ; U9.1 52.65,18.7 C25.1 ; C78.1 106.74,88.72 107.45,89.43 U32.1 ; C81.1 106.74,62.81 107.45,63.52 U31.1 ; v1(46.6,29.35) 46.65,29.3 U9.36 ; U2.1 81.89,19.38 C8.1 ; v1(61.72,26.29) 61.24,26.77 61.24,26.89 61.23,26.9 61.23,27.32 61.24,27.33 U4.36 ; C73.1 132.01,88.59 132.72,89.3 U30.1 ; C16.1 67.24,19.13 U4.1 ; C72.1 132.14,62.81 132.85,63.52 U29.1 ; U12.6 28.93,19.67 28.78,19.51 C31.1
  BOTTOM w0.381: v1(28.93,18.04) 28.93,18.04 28.78,18.2 C31.1 ; C8.1 v1(81.9,18.46) ; C32.1 v1(37.95,18.1) ; C26.1 v1(43.49,17.77) ; C30.1 v1(32.72,18.1) ; C17.1 v1(62.03,18.21) ; v1(76.84,18.45) 76.67,18.62 C9.1 ; C15.1 v1(58.08,18.21) ; C27.1 47.43,17.84 v1(47.37,17.78) ; C10.1 v1(72.73,18.46) ; C25.1 v1(52.66,17.77) ; C16.1 v1(67.25,18.21)
  BOTTOM w0.508: C82.1 106.74,137.99 v1(106.73,137.98) ; v1(132.01,112.84) 132.01,112.84 C64.1 ; v1(96.69,35.29) 96.69,32.89 v1(97.55,32.03) 98.38,32.03 101.03,34.68 v1(101.2,34.68) 103.64,37.12 v1(107.38,37.12) ; C72.1 132.14,61.66 v1(132.13,61.66) ; C78.1 106.74,87.57 v1(106.73,87.56) ; v1(132.12,138.29) 132.12,138.3 C65.1 ; C81.1 106.74,61.66 v1(106.73,61.66) ; C73.1 132.01,87.44 v1(132.01,87.44) ; J1.A27 v1(35.96,1.31) ; C85.1 106.74,112.46 v1(106.73,112.46) ; J1.A29 v1(33.42,1.31) ; J1.A28 v1(34.69,1.31) ; R88.2 104.83,89.81 v1(104.82,89.79)
  BOTTOM w0.635: v1(130.09,89.67) 130.11,89.68 R83.2 ; v1(130.2,140.52) 130.22,140.54 R76.2 ; v1(104.82,114.69) 104.83,114.7 R95.2 ; v1(104.82,63.89) 104.83,63.9 R89.2 ; v1(130.22,63.89) 130.23,63.9 R81.2 ; v1(104.82,140.21) 104.83,140.23 R94.2 ; v1(130.09,115.07) 130.11,115.08 R77.2
  vias: v1(29.59,4.73) v1(29.59,3.47) v1(86.24,129.73) v1(86.24,128.74)
VCC_5V0_HSE: length 3.6
  TOP w0.508: R66.1 v1(110.63,30.18)
  BOTTOM w0.508: J1.A3 v1(67.71,1.31) ; J1.A1 v1(70.25,1.31) ; J1.A2 v1(68.98,1.31)
  vias: v1(74.86,1.33) v1(76.07,1.31)
VCC_24V0: length 269.5
  BOTTOM w0.381: U32.9 112.91,89.93 C77.1 ; C69.1 138.18,115.2 U28.9 ; U27.9 138.29,140.66 C67.1 ; U29.9 138.31,64.02 C71.1 ; C87.1 112.91,114.82 U33.9 ; C74.1 138.18,89.8 U30.9 ; U34.9 112.91,140.35 C84.1 ; C80.1 112.91,64.02 U31.9
  BOTTOM w0.508: 146.69,114.94 147.58,115.82 147.58,137.54 144.78,140.33 142.75,140.33 ; 146.69,114.94 142.5,114.94 ; 146.69,114.94 147.58,114.05 147.58,90.68 146.56,89.66 ; 142.75,63.75 144.27,63.75 147.58,67.06 147.58,88.65 146.56,89.66 ; 98.68,120.27 97.28,121.67 97.28,144.27 99.57,146.56 117.1,146.56 v1(118.37,145.29) ; 98.68,120.27 98.68,99.57 100.2,98.04 ; 98.68,120.27 100.33,121.92 112.9,121.92 117.06,117.76 117.06,114.97 ; 146.56,89.66 142.75,89.66 ; 100.2,98.04 111.25,98.04 117.06,92.23 117.06,89.7 ; 100.2,98.04 99.06,96.9 99.06,82.68 111.76,69.98 113.92,69.98 116.71,67.18 116.71,63.63
  vias: v1(116.71,145.29) v1(116.71,144.27) v1(117.1,140.59) v1(117.1,139.57) v1(118.37,144.27) v1(121.54,30.73) v1(122.43,31.37) v1(123.32,30.73) v1(141.61,145.29) v1(141.61,144.27) v1(142.45,140.81) v1(142.46,139.9) v1(142.46,64.17) v1(142.47,63.26) v1(143.26,145.29) v1(143.26,144.27)
AIN_0: length 8.6
  TOP w0.152: C105.1 120.17,8.33 R128.2 ; C105.1 120.18,7.64 119.44,6.89 119.44,4.78 J12.15 ; C105.1 D10.2
AIN_2: length 3.9
  TOP w0.152: J12.6 105.38,6.06 C103.1 105.39,8.36 R126.1
AIN_4: length 6.2
  TOP w0.152: D9.2 110.23,8.5 C104.1 ; J12.10 108.93,7.59 C104.1 ; C104.1 108.91,8.48 R127.1
CQ_1: length 47.1
  TOP w0.152: DN1.4 134.28,130.06 129.73,130.06 v1(127.77,132.02)
  BOTTOM w0.152: v1(127.77,132.02) 127.8,132.05 D1.2 127.07,133.53 125.41,135.2 125.41,143.9 126.93,145.42 139.41,145.42 140.94,143.9 140.94,142.12 140.24,141.42 137.28,141.42 137.02,141.16 U27.8
CQ_2: length 48.2
  TOP w0.152: v1(127.69,107.02) 129.68,105.03 134.65,105.03 DN2.4
  BOTTOM w0.152: U28.8 136.9,115.7 137.24,116.04 140.82,116.04 141.38,116.6 141.38,118.85 139.92,120.31 126.65,120.31 125.6,119.26 125.6,109.6 127.13,108.07 D2.2 v1(127.69,107.02)
CQ_3: length 43.7
  TOP w0.152: v1(127.69,81.08) 127.71,81.08 129.29,79.5 134.53,79.5 DN3.4
  BOTTOM w0.152: U30.8 136.9,90.3 137.24,90.64 139.83,90.64 140.08,90.9 140.08,93.46 139.93,93.61 127.29,93.61 126.19,92.51 126.19,83.24 126.75,82.67 D4.2 v1(127.69,81.08)
CQ_4: length 45
  TOP w0.152: v1(127.82,55.75) 129.16,54.4 134.83,54.4 DN4.4
  BOTTOM w0.152: U29.8 137.03,64.52 137.37,64.86 140.15,64.86 140.52,65.23 140.52,67.38 139.24,68.66 126.57,68.66 125.6,67.69 125.6,59.16 127.82,56.95 D3.2 v1(127.82,55.75)
CQ_5: length 46.4
  TOP w0.152: v1(102.42,55.43) 102.44,55.43 103.76,54.1 109.13,54.1 DN5.4
  BOTTOM w0.152: U31.8 111.63,64.52 111.97,64.86 115.07,64.86 115.74,65.54 115.74,66.76 113.71,68.79 101.86,68.79 99.62,66.55 99.62,59.69 D6.2 v1(102.42,55.43)
CQ_6: length 43.9
  TOP w0.152: v1(102.49,81.41) 104.01,79.88 109.51,79.88 DN6.4
  BOTTOM w0.152: U32.8 111.63,90.43 111.97,90.77 114.81,90.77 115.19,91.15 115.19,92.71 113.67,94.23 101.6,94.23 100.84,93.47 100.84,84.2 102.24,82.8 D5.2 102.42,81.48 v1(102.49,81.41)
CQ_7: length 46.7
  TOP w0.152: DN7.4 109.51,105.28 103.63,105.28 v1(102.36,106.55)
  BOTTOM w0.152: U33.8 111.63,115.32 111.97,115.66 114.9,115.66 115.57,116.33 115.57,118.36 113.92,120.02 101.22,120.02 100.08,118.87 100.08,110.03 D8.2 102.42,106.61 v1(102.36,106.55)
CQ_8: length 46.9
  TOP w0.152: v1(102.42,131.65) 103.89,130.17 109,130.17 DN8.4
  BOTTOM w0.152: v1(102.42,131.65) D7.2 101.86,133.22 99.95,135.13 99.95,144.59 100.8,145.44 113.01,145.44 115.19,143.26 115.19,141.7 114.68,141.19 111.97,141.19 111.63,140.85 U34.8
DI_1: length 162.9
  TOP w0.152: R111.1 124.06,14.49 129.41,9.14 132.46,9.14 132.84,9.53 132.84,11.56 134.11,12.83 J21.3
  BOTTOM w0.152: J21.3 133.73,12.83 132.97,12.06 132.97,9.4 132.34,8.76 130.05,8.76 128.65,10.16 128.65,18.41 129.92,19.68 129.92,23.19 133.94,27.21 133.94,38.07 122.23,49.78 122.23,90.86 124.84,93.47 124.84,121.67 131.32,128.14 131.32,134.17 DN1.2
DI_2: length 124.3
  TOP w0.152: R112.1 127.76,16.38 128.4,15.75 128.4,13.59 J21.2
  BOTTOM w0.152: DN2.2 125.35,102.8 125.35,92.96 122.81,90.42 122.81,49.63 134.37,38.07 134.37,26.8 130.3,22.73 130.3,19.43 130.05,19.18 130.05,11.94 130.3,11.68 J21.2
DI_3: length 91.8
  TOP w0.152: J21.5 132.97,16.64 130.94,16.64 129.13,18.44 R113.1
  BOTTOM w0.152: DN3.2 124.08,76.13 124.08,48.95 134.7,38.33 134.7,24.59 132.97,22.86 132.97,16.64 J21.5
DI_4: length 75.2
  TOP w0.152: J21.4 132.97,14.1 134.62,14.1 135.51,14.99 135.51,18.92 135.26,19.18 130.56,19.18 130.3,18.92 125.1,18.92 123.54,20.48 R114.1
  BOTTOM w0.152: DN4.2 130.68,57.33 130.68,52.7 135.89,47.5 135.89,25.74 135.64,25.48 135.64,14.48 135.13,13.97 132.97,13.97 131.83,12.83 J21.4
DI_5: length 70.9
  TOP w0.152: R115.1 124.65,22.29 127.26,19.68 v1(128.02,19.68)
  L03_SIG1 w0.152: v1(128.02,19.68) 128.65,19.05 133.1,19.05 J21.7
  BOTTOM w0.152: v1(128.02,19.68) 127.26,19.68 126.37,20.57 126.37,25.15 130.3,29.08 130.3,36.83 113.92,53.21 107.57,53.21 105.41,55.37 105.41,57.46 DN5.2
DI_6: length 116.9
  TOP w0.152: R116.1 v1(103.79,23.59)
  L03_SIG1 w0.152: v1(103.79,23.59) 104.43,24.22 120.81,24.22 121.54,23.5 127.89,23.5 v1(128.02,23.37) 131.19,23.37 132.08,22.48 134.88,22.48 135.38,21.97 135.38,17.14 134.71,16.47 133.44,16.47 132.34,15.37 J21.6
  BOTTOM w0.152: v1(128.02,23.37) 130.68,26.04 130.68,37.08 118.49,49.28 118.49,67.44 105.79,80.14 105.79,83.24 DN6.2
DI_7: length 134.5
  TOP w0.152: R117.1 v1(103.75,21.54)
  L03_SIG1 w0.152: J21.8 128.65,17.91 127.51,19.05 v1(127.51,21.84) 127.51,21.97 127.31,22.17 104.37,22.17 v1(103.75,21.54)
  BOTTOM w0.152: DN7.2 105.28,108.13 105.28,105.92 119.38,91.82 119.38,49.02 131.07,37.34 131.07,25.27 127.64,21.84 v1(127.51,21.84)
DI_8: length 168.6
  TOP w0.152: R118.1 v1(103.84,19.49)
  L03_SIG1 w0.152: v1(129.41,20.32) 129.54,20.45 J21.10
  BOTTOM w0.152: DN8.2 107.06,135.76 105.67,134.37 105.67,130.81 108.33,128.14 110.62,128.14 119.07,119.69 119.07,94.29 121.29,92.08 121.29,48.06 133.35,35.99 133.35,27.05 129.41,23.11 v1(129.41,20.32) 127.38,18.29 127.38,14.22 125.6,12.45 120.52,12.45 119.51,13.46 115.57,13.46 115.06,13.97 113.03,13.97 108.59,18.41 104.78,18.41 103.84,19.35 v1(103.84,19.49)
EEPROM0_A0: length 4.7
  TOP w0.152: U1.1 86.78,34.21 R2.2 86.2,34.81 R6.1
EEPROM0_A1: length 4.9
  TOP w0.152: R7.1 R3.2 86.78,32.94 U1.2
EEPROM0_A2: length 5
  TOP w0.152: R8.1 R4.2 87.17,31.67 U1.3
EEPROM0_WP: length 1.7
  TOP w0.152: U1.7 R5.2
EN_L+1: length 78.3
  TOP w0.152: v1(57.15,33.53) 57.74,32.94 U7.44 ; U36.5 v1(68.58,98.07)
  L03_SIG1 w0.152: v1(68.58,98.07) 68.15,98.5 65.8,98.5 62.49,95.18 62.49,88.9 57.27,83.69 57.27,33.65 v1(57.15,33.53)
EN_L+2: length 76.9
  TOP w0.152: U7.39 60.24,32.34 v1(60.07,32.51) ; U36.6 69.23,97.36 v1(68.65,96.79)
  L03_SIG1 w0.152: v1(60.07,32.51) 60.2,32.64 60.2,34.75 59.84,35.11 59.84,84.02 60.2,84.38 60.2,84.46 64.26,88.52 64.26,95.17 65.88,96.79 v1(68.65,96.79)
EN_L+3: length 74.7
  TOP w0.152: U7.32 v1(63.74,32.26) ; v1(67.36,95.44) 67.93,96.01 U36.4
  L03_SIG1 w0.152: v1(67.36,95.44) 66.91,95.89 65.91,95.89 65.28,95.26 65.28,87.63 63.31,85.66 63.31,32.7 63.74,32.27 v1(63.74,32.26)
EN_L+4: length 72.8
  TOP w0.152: v1(66.17,95.46) 67.28,96.57 U36.3 ; v1(63.74,33.4) 64.24,32.9 U7.31
  L03_SIG1 w0.152: v1(66.17,95.46) 66.17,87.89 63.74,85.46 v1(63.74,33.4)
EN_L+5: length 92.6
  TOP w0.152: U7.45 57.24,32.29 v1(56.9,32.64) ; U35.5 v1(83.15,98.07)
  L03_SIG1 w0.152: v1(83.15,98.07) 82.72,98.5 79.59,98.5 78.57,97.47 65.6,97.47 63.76,95.63 63.76,89.54 57.6,83.38 57.6,43.33 57.62,43.32 57.62,33.15 57.11,32.64 v1(56.9,32.64)
EN_L+6: length 82.6
  TOP w0.152: U7.26 66.74,31.81 v1(66.3,32.26) ; U35.6 83.8,97.7 v1(83.15,97.05)
  L03_SIG1 w0.152: v1(83.15,97.05) 80.3,94.2 75.66,94.2 65.15,83.69 65.15,35.18 66.69,33.64 66.69,32.66 v1(66.3,32.26)
EN_L+7: length 90.1
  TOP w0.152: v1(61.34,32.38) 60.74,31.79 U7.38 ; v1(81.85,97.05) 82.5,97.7 U35.4
  L03_SIG1 w0.152: v1(61.34,32.38) 61.34,34.04 60.14,35.24 60.14,83.89 64.64,88.39 64.64,95.12 65.72,96.2 80.99,96.2 v1(81.85,97.05)
EN_L+8: length 82.6
  TOP w0.152: U35.3 v1(81.85,98.07) ; v1(66.26,33.27) 67.24,32.29 U7.25
  L03_SIG1 w0.152: v1(66.26,33.27) 65.41,33.27 64.84,33.84 64.84,83.82 75.53,94.51 79.91,94.51 82.28,96.88 82.28,97.64 v1(81.85,98.07)
EN_PHY_1: length 215.6
  TOP w0.152: TP9.1 123.81,142.1 125.04,143.33 v1(126.88,143.33)
  L03_SIG1 w0.152: v1(126.88,143.33) 128.71,143.33 132.72,139.32 135.03,139.32 141.35,132.99 141.35,71.88 140.13,70.66 140.13,55.22 126.61,41.7 116.12,41.7 101.33,26.91 82.69,26.91 82.58,27.03 80.14,27.03 76.67,23.56 71.57,23.56 70.59,22.58 67.03,22.58 66.35,23.26 55.87,23.26 v1(55.75,23.14)
  BOTTOM w0.152: v1(126.88,143.33) 127.71,144.16 130.83,144.16 132.84,142.16 U27.5 ; U9.45 51.15,26.58 54.59,23.14 v1(55.75,23.14)
EN_PHY_2: length 175.6
  TOP w0.152: TP12.1 123.42,117.87 v1(126.76,117.87)
  L03_SIG1 w0.152: v1(126.76,117.87) 126.33,117.44 126.33,111.7 132.46,105.57 132.46,90.04 130.18,87.76 130.18,72.52 133.73,68.96 133.73,64.39 131.83,62.48 130.05,62.48 98.67,31.11 77.85,31.11 75.19,28.45 75.19,27.33 72.87,25.02 68.33,25.02 66.93,23.62 53.49,23.62 v1(53.04,23.18)
  BOTTOM w0.152: U28.5 132.72,116.7 130.72,118.71 127.6,118.71 v1(126.76,117.87) ; v1(53.04,23.18) 50.65,25.57 U9.44
EN_PHY_3: length 134.9
  TOP w0.152: v1(126.76,92.47) 126.51,92.47 125.28,91.24 TP15.1
  L03_SIG1 w0.152: v1(48.65,25.66) 59.68,25.66 61.94,27.91 66.65,27.91 76.89,38.15 96.41,38.15 123.06,64.81 123.06,88.77 v1(126.76,92.47)
  BOTTOM w0.152: v1(126.76,92.47) 127.02,92.47 127.51,92.96 131.06,92.96 132.72,91.3 U30.5 ; v1(48.65,25.66) 48.15,26.16 U9.39
EN_PHY_4: length 112.7
  TOP w0.152: TP18.1 124.56,67.7 v1(126.8,67.7)
  L03_SIG1 w0.152: v1(126.8,67.7) 96.94,37.85 77.01,37.85 66.73,27.56 63.08,27.56 62.74,27.22 62.74,26.69 60.92,24.87 v1(48.52,24.87)
  BOTTOM w0.152: U29.5 132.85,65.52 130.67,67.7 v1(126.8,67.7) ; U9.38 47.65,25.75 v1(48.52,24.87)
EN_PHY_5: length 100.5
  TOP w0.152: TP21.1 98.15,66.69 v1(101.49,66.69)
  L03_SIG1 w0.152: v1(101.49,66.69) 101.92,66.26 101.92,64.96 91.54,54.58 91.54,42.37 90.17,41 73.36,41 68.53,36.17 68.53,32.16 66.22,29.84 59.54,29.84 58.98,29.29 48.44,29.29 46.97,30.76 v1(44.15,30.76)
  BOTTOM w0.152: U9.32 44.65,30.26 v1(44.15,30.76) ; U31.5 107.45,65.52 105.44,67.53 102.33,67.53 v1(101.49,66.69)
EN_PHY_6: length 136.4
  TOP w0.152: TP24.1 98.15,92.6 v1(101.49,92.6)
  L03_SIG1 w0.152: v1(44.07,29.21) 45.06,28.22 59.34,28.22 59.97,28.85 66.73,28.85 76.64,38.76 96.16,38.76 112.26,54.86 112.26,72.78 101.06,83.98 101.06,92.17 v1(101.49,92.6)
  BOTTOM w0.152: v1(44.07,29.21) 44.15,29.13 U9.31 ; v1(101.49,92.6) 102.33,93.43 105.44,93.43 107.45,91.43 U32.5
EN_PHY_7: length 166.9
  TOP w0.152: v1(101.49,117.49) 98.15,117.49 TP27.1
  L03_SIG1 w0.152: v1(41.15,25.66) 40.72,26.09 40.72,28.4 42.55,30.23 44.96,30.23 46.27,28.92 59.04,28.92 59.59,29.46 66.27,29.46 68.84,32.03 68.84,36.04 73.48,40.69 90.3,40.69 91.85,42.24 91.85,51.97 102.82,62.94 102.82,70.28 92.86,80.24 92.86,108.1 100.46,115.7 101.35,115.7 101.92,116.27 101.92,117.06 v1(101.49,117.49)
  BOTTOM w0.152: U9.26 41.65,26.16 v1(41.15,25.66) ; U33.5 107.45,116.32 105.44,118.33 102.33,118.33 v1(101.49,117.49)
